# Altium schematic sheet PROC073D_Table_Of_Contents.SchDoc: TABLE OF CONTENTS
size 431 x 279 mm; Date: Not shown in title block; ApprovedBy: Not shown in title block; CheckedBy: Not shown in title block; Author: Not shown in title block; CompanyName: Not shown in title block; DrawnBy: Charles F. Oladimeji; Engineer: Not shown in title block; Organization: Not shown in title block; Address1: Not shown in title block; Address2: Not shown in title block; Address3: Not shown in title block; Address4: Not shown in title block; DocumentNumber: 2; Revision: Use project parameter SCH_Rev; SheetNumber: 2; SheetTotal: 13; PageSetup: Record=PageOptions¦CenterHorizontal=True¦CenterVertical=True¦PrintScale=1.00¦XCorrection=1.00¦YCorrection=1.00¦PrintKind=0¦BorderSize=5000000¦LeftOffset=0¦BottomOffset=0¦Orientation=2¦PaperLength=1000¦PaperWidth=1000¦Scale=100¦PaperSource=15¦PrintQuality=600¦MediaType=1¦DitherType=10¦PaperKind=Letter¦PrintScaleMode=1
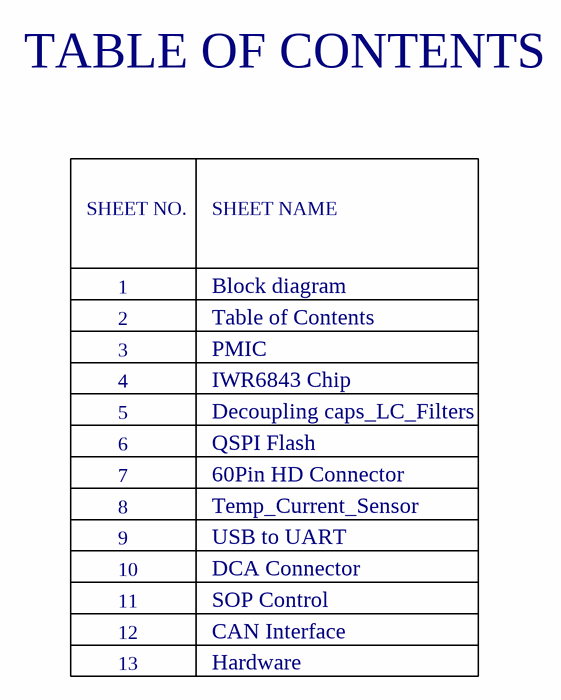
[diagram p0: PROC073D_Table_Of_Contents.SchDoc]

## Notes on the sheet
- TABLE OF CONTENTS
- SHEET NO.
- SHEET NAME
- 1
- 2
- 3
- Table of Contents
- Block diagram
- PMIC
- 4
- 5
- IWR6843 Chip
- Decoupling caps_LC_Filters
- 7
- 8
- 6
- QSPI Flash
- 60Pin HD Connector
- Temp_Current_Sensor
- 9
- 10
- USB to UART
- DCA Connector
- 11
- 12
- 13
- SOP Control
- CAN Interface
- Hardware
